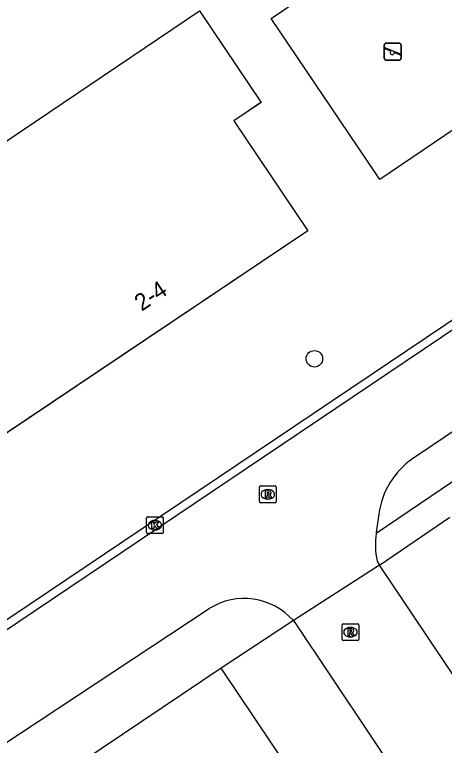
# Model space of a CAD drawing. Extents: x 158797 to 159887, y 384318 to 385255.
# Drawn here: x 159059.54 to 159085.01, y 384529.23 to 384572.51 of the extents above; entities that cross this region are included whole.
import ezdxf

# ---------------------------------------------------------------- set-up
doc = ezdxf.new("R2010")
doc.units = 0
for name, color, linetype in [('IMGEO_Boom', 7, 'Continuous'), ('IMGEO_Groenvoorziening', 7, 'Continuous'), ('IMGEO_Kolk', 7, 'Continuous'), ('IMGEO_Pand', 7, 'Continuous'), ('IMGEO_Pand_nummerreeks', 7, 'Continuous'), ('IMGEO_Pand_vergunning_verleend', 7, 'Continuous'), ('IMGEO_Rijbaan_lokaal_open', 7, 'Continuous'), ('IMGEO_Rioolput', 7, 'Continuous'), ('IMGEO_Speelvoorziening', 7, 'Continuous'), ('IMGEO_Voetpad_open', 7, 'Continuous')]:
    doc.layers.add(name, color=color, linetype=linetype)

msp = doc.modelspace()

# ---------------------------------------------------------------- linework, layer by layer
at = {"layer": 'IMGEO_Boom'}
msp.add_circle((159077.305, 384552.126), 0.489, dxfattribs=at)
at = {"layer": 'IMGEO_Groenvoorziening'}
msp.add_lwpolyline([(159074.744, 384572.276), (159083.027, 384577.88), (159089.501, 384568.358), (159081.187, 384562.743), (159080.913, 384563.148), (159074.744, 384572.276)], dxfattribs=at)
at = {"layer": 'IMGEO_Kolk'}
for p, q in [((159067.429, 384542.769), (159068.281, 384542.769)), ((159067.354, 384541.843), (159067.354, 384542.695)), ((159067.842, 384542.549), (159067.867, 384542.549)), ((159068.355, 384542.695), (159068.355, 384541.843)), ((159067.865, 384541.989), (159067.84, 384541.989)), ((159068.281, 384541.769), (159067.429, 384541.769))]:
    msp.add_line(p, q, dxfattribs=at)
for points in [[(159067.429, 384542.769), (159068.281, 384542.769)], [(159067.354, 384541.843), (159067.354, 384542.695)], [(159067.675, 384542.469), (159067.798, 384542.469), (159067.798, 384542.318), (159067.928, 384542.469), (159068.092, 384542.469), (159067.946, 384542.318), (159068.099, 384542.069), (159067.947, 384542.069), (159067.862, 384542.233), (159067.798, 384542.166), (159067.798, 384542.069), (159067.675, 384542.069), (159067.675, 384542.469)], [(159068.355, 384542.695), (159068.355, 384541.843)], [(159068.281, 384541.769), (159067.429, 384541.769)]]:
    msp.add_lwpolyline(points, dxfattribs=at)
for centre, start, end in [((159067.431, 384542.693), 91.552, 178.448), ((159067.431, 384542.693), 91.552, 178.448), ((159068.279, 384542.693), 1.552, 88.448), ((159068.279, 384542.693), 1.552, 88.448), ((159067.431, 384541.845), 181.552, 268.448), ((159067.431, 384541.845), 181.552, 268.448), ((159068.279, 384541.845), 271.552, 358.448), ((159068.279, 384541.845), 271.552, 358.448)]:
    msp.add_arc(centre, 0.0765, start, end, dxfattribs=at)
for centre, major_axis, ratio, start_param, end_param in [((159067.841, 384542.269), (-0.387, 0.002), 0.722429, 4.712389, 7.853982), ((159067.866, 384542.269), (-0.39, 0.002), 0.717154, 1.570796, 4.712389)]:
    msp.add_ellipse(centre, major_axis=major_axis, ratio=ratio, start_param=start_param, end_param=end_param, dxfattribs=at)
at = {"layer": 'IMGEO_Pand'}
for points in [[(159070.501, 384572.739), (159074.142, 384567.305), (159072.525, 384566.217), (159076.912, 384559.695), (159050.979, 384542.317), (159045.281, 384550.539), (159050.945, 384554.464), (159048.565, 384557.949), (159070.501, 384572.739)], [(159071.774, 384533.799), (159050.67, 384519.624)], [(159126.029, 384461.936), (159121.905, 384459.166), (159071.774, 384533.799)]]:
    msp.add_lwpolyline(points, dxfattribs=at)
at = {"layer": 'IMGEO_Pand_vergunning_verleend'}
msp.add_lwpolyline([(159074.142, 384567.305), (159074.124, 384567.293), (159073.385, 384566.795), (159072.525, 384566.217), (159076.912, 384559.695), (159066.003, 384552.385), (159056.131, 384545.77), (159050.979, 384542.317), (159045.281, 384550.539), (159045.719, 384550.843), (159050.945, 384554.464), (159049.721, 384556.256), (159048.565, 384557.949), (159070.501, 384572.739), (159074.142, 384567.305)], dxfattribs=at)
at = {"layer": 'IMGEO_Rijbaan_lokaal_open'}
for points in [[(159112.09, 384571.725), (159039.789, 384523.103), (159038.887, 384522.562)], [(159054.773, 384533.798), (159107.496, 384569.245)], [(159102.05, 384558.954), (159083.109, 384546.206)], [(159081.12, 384542.935), (159080.969, 384541.834), (159080.965, 384541.809), (159080.962, 384541.784)], [(159081.017, 384540.159), (159081.037, 384540.102), (159081.166, 384539.91)], [(159081.166, 384539.91), (159076.06, 384536.619)], [(159125.843, 384482.068), (159121.763, 384479.19), (159114.556, 384490.118), (159081.78, 384538.994), (159081.166, 384539.91)], [(159005.109, 384493.811), (159040.833, 384517.38), (159048.701, 384522.571), (159071.071, 384537.329)], [(159076.06, 384536.619), (159126.029, 384461.936)]]:
    msp.add_lwpolyline(points, dxfattribs=at)
for centre, radius, start, end in [((159085.882, 384542.279), 4.807, 125.2339, 172.1609), ((159085.544, 384541.126), 4.63, 171.8247, 192.0523), ((159073.147, 384534.031), 3.897, 41.6121, 122.1888)]:
    msp.add_arc(centre, radius, start, end, dxfattribs=at)
at = {"layer": 'IMGEO_Rioolput'}
for p, q in [((159074.047, 384543.67), (159074.047, 384544.522)), ((159074.122, 384544.596), (159074.974, 384544.596)), ((159075.048, 384544.522), (159075.048, 384543.67)), ((159074.535, 384544.376), (159074.56, 384544.376)), ((159074.974, 384543.596), (159074.122, 384543.596)), ((159074.558, 384543.816), (159074.533, 384543.816)), ((159078.942, 384535.51), (159078.942, 384536.362)), ((159079.017, 384536.436), (159079.869, 384536.436)), ((159079.943, 384536.362), (159079.943, 384535.51)), ((159079.43, 384536.216), (159079.455, 384536.216)), ((159079.869, 384535.436), (159079.017, 384535.436)), ((159079.453, 384535.656), (159079.428, 384535.656))]:
    msp.add_line(p, q, dxfattribs=at)
for points in [[(159074.047, 384543.67), (159074.047, 384544.522)], [(159074.122, 384544.596), (159074.974, 384544.596)], [(159075.048, 384544.522), (159075.048, 384543.67)], [(159074.636, 384544.294), (159074.384, 384544.296), (159074.384, 384543.896)], [(159074.384, 384543.896), (159074.508, 384543.896), (159074.508, 384544.058), (159074.519, 384544.058)], [(159074.562, 384544.215), (159074.508, 384544.215), (159074.508, 384544.134)], [(159074.508, 384544.134), (159074.56, 384544.134)], [(159074.566, 384544.029), (159074.637, 384543.896), (159074.777, 384543.896), (159074.712, 384544.022)], [(159074.974, 384543.596), (159074.122, 384543.596)], [(159078.942, 384535.51), (159078.942, 384536.362)], [(159079.017, 384536.436), (159079.869, 384536.436)], [(159079.943, 384536.362), (159079.943, 384535.51)], [(159079.531, 384536.134), (159079.279, 384536.136), (159079.279, 384535.736)], [(159079.279, 384535.736), (159079.403, 384535.736), (159079.403, 384535.898), (159079.414, 384535.898)], [(159079.457, 384536.055), (159079.403, 384536.055), (159079.403, 384535.974)], [(159079.403, 384535.974), (159079.455, 384535.974)], [(159079.461, 384535.869), (159079.532, 384535.736), (159079.672, 384535.736), (159079.607, 384535.862)], [(159079.869, 384535.436), (159079.017, 384535.436)]]:
    msp.add_lwpolyline(points, dxfattribs=at)
for centre, radius, start, end in [((159074.124, 384544.52), 0.0765, 91.552, 178.448), ((159074.124, 384544.52), 0.0765, 91.552, 178.448), ((159074.972, 384544.52), 0.0765, 1.552, 88.448), ((159074.972, 384544.52), 0.0765, 1.552, 88.448), ((159074.518, 384544.005), 0.0533, 26.0293, 88.6989), ((159074.544, 384544.323), 0.19, 274.7715, 282.9687), ((159074.568, 384544.119), 0.0964, 77.0061, 93.1865), ((159074.582, 384544.176), 0.0378, 276.6634, 79.6772), ((159074.635, 384544.184), 0.109, 350.3612, 89.416), ((159074.633, 384544.184), 0.112, 277.5842, 350.9817), ((159074.617, 384543.969), 0.108, 29.5134, 73.7905), ((159074.124, 384543.672), 0.0765, 181.552, 268.448), ((159074.124, 384543.672), 0.0765, 181.552, 268.448), ((159074.972, 384543.672), 0.0765, 271.552, 358.448), ((159074.972, 384543.672), 0.0765, 271.552, 358.448), ((159079.019, 384536.36), 0.0765, 91.552, 178.448), ((159079.019, 384536.36), 0.0765, 91.552, 178.448), ((159079.867, 384536.36), 0.0765, 1.552, 88.448), ((159079.867, 384536.36), 0.0765, 1.552, 88.448), ((159079.413, 384535.845), 0.0533, 26.0293, 88.6989), ((159079.439, 384536.163), 0.19, 274.7715, 282.9687), ((159079.463, 384535.959), 0.0964, 77.0061, 93.1865), ((159079.477, 384536.016), 0.0378, 276.6634, 79.6772), ((159079.53, 384536.024), 0.109, 350.3612, 89.416), ((159079.528, 384536.024), 0.112, 277.5842, 350.9817), ((159079.512, 384535.809), 0.108, 29.5134, 73.7905), ((159079.019, 384535.512), 0.0765, 181.552, 268.448), ((159079.019, 384535.512), 0.0765, 181.552, 268.448), ((159079.867, 384535.512), 0.0765, 271.552, 358.448), ((159079.867, 384535.512), 0.0765, 271.552, 358.448)]:
    msp.add_arc(centre, radius, start, end, dxfattribs=at)
for centre, major_axis, ratio, start_param, end_param in [((159074.534, 384544.096), (-0.387, 0.002), 0.722429, 4.712389, 7.853982), ((159074.559, 384544.096), (-0.39, 0.002), 0.717154, 1.570796, 4.712389), ((159079.429, 384535.936), (-0.387, 0.002), 0.722429, 4.712389, 7.853982), ((159079.454, 384535.936), (-0.39, 0.002), 0.717154, 1.570796, 4.712389)]:
    msp.add_ellipse(centre, major_axis=major_axis, ratio=ratio, start_param=start_param, end_param=end_param, dxfattribs=at)
at = {"layer": 'IMGEO_Speelvoorziening'}
for p, q in [((159081.446, 384569.914), (159081.446, 384570.714)), ((159081.446, 384570.714), (159081.446, 384569.914)), ((159081.829, 384570.342), (159081.49, 384570.479)), ((159081.515, 384570.539), (159082.391, 384570.186)), ((159081.546, 384570.814), (159082.336, 384570.814)), ((159082.336, 384570.814), (159081.546, 384570.814)), ((159082.436, 384570.714), (159082.436, 384569.914)), ((159082.436, 384569.914), (159082.436, 384570.714)), ((159082.367, 384570.126), (159082.027, 384570.263)), ((159082.336, 384569.814), (159081.546, 384569.814)), ((159081.546, 384569.814), (159082.336, 384569.814))]:
    msp.add_line(p, q, dxfattribs=at)
for centre, radius, start, end in [((159081.546, 384570.714), 0.1, 90, 180), ((159081.546, 384570.714), 0.1, 90, 180), ((159081.503, 384570.509), 0.0327, 68.078, 248.078), ((159082.336, 384570.714), 0.1, 0, 90), ((159082.336, 384570.714), 0.1, 360, 90), ((159081.908, 384570.252), 0.12, 130.9928, 5.1632), ((159082.379, 384570.156), 0.0327, 248.078, 68.078), ((159081.546, 384569.914), 0.1, 180, 270), ((159081.546, 384569.914), 0.1, 180, 270), ((159082.336, 384569.914), 0.1, 270, 0), ((159082.336, 384569.914), 0.1, 270, 0)]:
    msp.add_arc(centre, radius, start, end, dxfattribs=at)
at = {"layer": 'IMGEO_Voetpad_open'}
for points in [[(159106.635, 384559.148), (159080.962, 384541.784)], [(159081.166, 384539.91), (159085.318, 384542.737)], [(159076.06, 384536.619), (159071.774, 384533.799)]]:
    msp.add_lwpolyline(points, dxfattribs=at)

# ---------------------------------------------------------------- texts
at = {"layer": 'IMGEO_Pand_nummerreeks'}
msp.add_text('2-4', height=1, rotation=33.8274, dxfattribs=at).set_placement((159067.073, 384554.907))

doc.saveas('drawing.dxf')
